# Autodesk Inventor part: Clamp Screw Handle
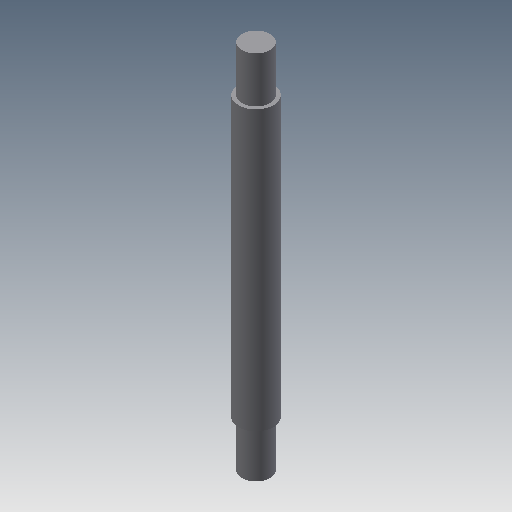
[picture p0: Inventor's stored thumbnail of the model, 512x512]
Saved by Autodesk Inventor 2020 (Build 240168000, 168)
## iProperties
Created: 2002-02
Part Number: Clamp Screw Handle
Document SubType Name: Modeling
Designer: ***
Density: 1 g/cm^3
Material: Generic
Appearance: Default
Control State: 0
Master: False
Checked Out: False
Shininess: 77.0
Length Units: 11269
Angle Units: 11279
Time Units: 11290
Mass Units: 11283
Length Display Precision: 3
Angle Display Precision: 2
Compacted: True
Density: 0.0
Volumn: 0.0
Area: 0.0
PropertySet Name: Model Information
Author: ***
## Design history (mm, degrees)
sketch "Sketch1"
  geometry: L1 (0, 105)-(4, 105); L2 (4, 105)-(4, 92); L3 (4, 92)-(5, 92); L4 (5, 92)-(5, 13); L5 (5, 13)-(4, 13); L6 (4, 13)-(4, 0); L7 (4, 0)-(0, 0); L8 (0, 0)-(0, 105)
  constraints: 16 end point, 5 parallel, 2 equal length, 1 collinear, 1 horizontal, 1 perpendicular
  dimensions: "d0" = 10 diameter of L4 L8; "d1" = 8 diameter of L2 L8; "d2" = 13 distance of L1.end L2.end; "d3" = 79 distance of L3.end L4.end
revolve "Revolution1" sketch "Sketch1" stored, may be unused: angle "d4" = 90 deg
body "Solid1"
